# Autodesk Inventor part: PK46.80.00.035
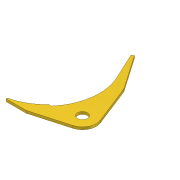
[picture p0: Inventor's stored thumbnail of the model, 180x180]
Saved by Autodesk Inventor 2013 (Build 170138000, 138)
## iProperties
Shininess: 64.0
Length Units: 11269
Angle Units: 11279
Time Units: 11290
Mass Units: 11283
Length Display Precision: 3
Angle Display Precision: 2
Compacted: True
Part Number: PK46.80.00.035
Document SubType Name: Modeling
Created: 2005-01
Material: Steel, Mild
Designer: SAlex
Manufacturer: Standard
Standards Organization: Custom
Density: 7.86 g/cm^3
Mass: 17355.9 g
Surface Area: 2723.6 cm^2
Volume: 2208.13 cm^3
Density: 0.0
Volumn: 0.0
Area: 0.0
PropertySet Name: Model Information
Control State: 0
Master: False
Checked Out: False
Checked Out Date: 2008-10-15
Last Check In Date: 2008-10-15
Author: SAlex
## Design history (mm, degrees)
sketch "Sketch1"
  geometry: L1 (-420, -188)-(-260, -188); L2 (-260, -188)-(29.987, -105.834); L3 (-20, 350)-(102.306, 40.417); L4 (-20, 350)-(-206.915, 620.625); L5 (-206.915, 620.625)-(-225.041, 612.172); L6 (-225.041, 612.172)-(-125.725, 399.19); L7 (-420, -177.95)-(-420, -188); L8 (-510, 220)-(-125.725, 399.19); L9 (-211.37, -58)-(-189.856, -58); C1 r 40 at (0, 0); A1 r 110 centre (0, 0) between (29.987, -105.834) and (102.306, 40.417); A2 r 408 centre (-510, 220) between (-420, -177.95) and (-211.37, -58); A3 r 424 centre (-510, 220) between (-189.856, -58) and (-125.725, 399.19)
  constraints: 18 end point, 6 point on circle, 4 centre point, 3 perpendicular, 3 tangent, 1 coincident, 1 horizontal, 1 other
  dimensions: "d0" = 80 diameter of C1; "d1" = 110 radius of A1; "d3" = 188 distance from line of L1 A1.centre; "d25" = 510 horizontal distance of L8.start C1.centre; "d26" = 220 vertical distance of L8.start C1.centre; "d29" = 90 distance from line of L7 L8.start; "d30" = 160 distance of L1.start L1.end; "d31" = 235 distance of L5.end L6.end; "d32" = 130 vertical distance of L3.start L8.start; "d33" = 490 horizontal distance of L3.start L8.start; "d35" = 115 deg angle of L7 L8; "d36" = 20 distance of L4.end L5.end; "d38" = 408 radius of A2; "d39" = 424 radius of A3; "d40" = 130 distance between parallel lines of L9 L1
extrude "Extrusion1" new body sketch "Sketch1" distance "d10" = 20; taper "d11" = 0 deg
body "Solid1"
other parameters: "d28" = 408
